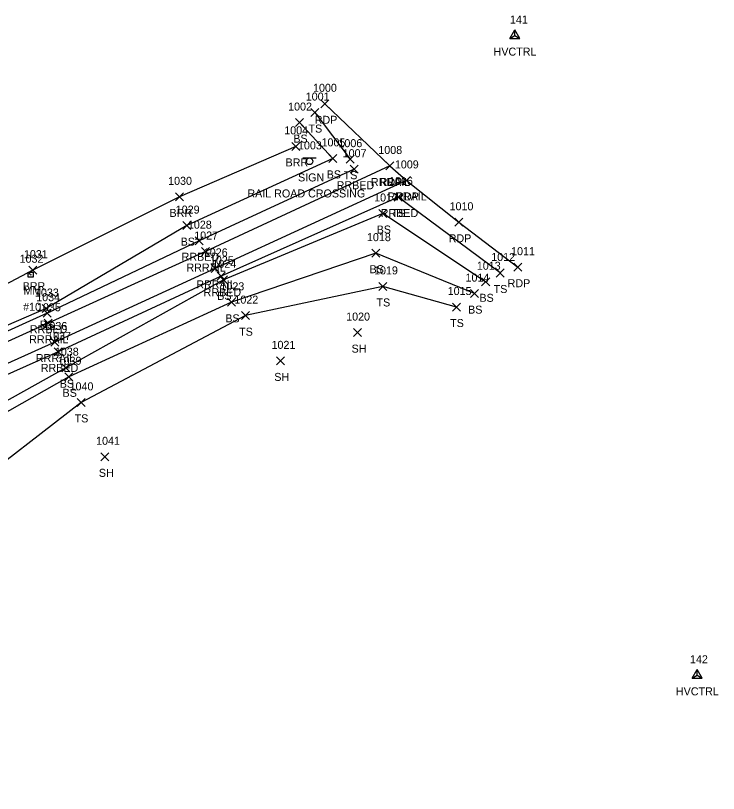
# Model space of a CAD drawing. Extents: x 1640777 to 1641692, y 610911 to 611377.
# Drawn here: x 1641516.6 to 1641692, y 611162.7 to 611356.9 of the extents above; entities that cross this region are included whole.
import ezdxf

# ---------------------------------------------------------------- set-up
doc = ezdxf.new("R2010")
doc.units = 0
for name, color, linetype in [('C_A', 7, 'Continuous'), ('C_I', 7, 'Continuous'), ('CPSM', 7, 'Continuous'), ('L_A', 7, 'Continuous'), ('L_I', 7, 'Continuous'), ('L_TIC', 7, 'Continuous'), ('LABL', 7, 'Continuous'), ('LELB', 7, 'Continuous'), ('P_A', 7, 'Continuous'), ('P_I', 7, 'Continuous'), ('P_TIC', 7, 'Continuous'), ('PET', 7, 'Continuous'), ('R_A', 7, 'Continuous'), ('R_I', 7, 'Continuous'), ('R_TIC', 7, 'Continuous'), ('RR', 7, 'Continuous'), ('RRB', 7, 'Continuous'), ('S_A', 7, 'Continuous'), ('S_C', 7, 'Continuous'), ('S_I', 7, 'Continuous'), ('SRM', 7, 'Continuous'), ('SSGN', 7, 'Continuous')]:
    doc.layers.add(name, color=color, linetype=linetype)

msp = doc.modelspace()

# ---------------------------------------------------------------- linework, layer by layer
at = {"layer": 'CPSM'}
for p, q in [((1641639.94, 611351.19), (1641641.19, 611353.35)), ((1641642.44, 611351.19), (1641641.19, 611353.35)), ((1641641.19, 611351.91), (1641641.19, 611353.35)), ((1641639.94, 611351.19), (1641641.19, 611351.91)), ((1641639.94, 611351.19), (1641642.44, 611351.19)), ((1641641.19, 611351.91), (1641641.19, 611351.91)), ((1641641.19, 611351.91), (1641642.44, 611351.19)), ((1641685.45, 611191.48), (1641686.7, 611193.64)), ((1641687.95, 611191.48), (1641686.7, 611193.64)), ((1641686.7, 611192.2), (1641686.7, 611193.64)), ((1641685.45, 611191.48), (1641686.7, 611192.2)), ((1641685.45, 611191.48), (1641687.95, 611191.48)), ((1641686.7, 611192.2), (1641686.7, 611192.2)), ((1641686.7, 611192.2), (1641687.95, 611191.48))]:
    msp.add_line(p, q, dxfattribs=at)
at = {"layer": 'L_TIC'}
for points in [[(1641590.27, 611331.69), (1641592.27, 611333.69)], [(1641592.27, 611331.69), (1641590.27, 611333.69)], [(1641586.44, 611329.19), (1641588.44, 611331.19)], [(1641588.44, 611329.19), (1641586.44, 611331.19)], [(1641585.48, 611323.25), (1641587.48, 611325.25)], [(1641587.48, 611323.25), (1641585.48, 611325.25)], [(1641594.78, 611320.25), (1641596.78, 611322.25)], [(1641596.78, 611320.25), (1641594.78, 611322.25)], [(1641599.06, 611320.05), (1641601.06, 611322.05)], [(1641601.06, 611320.05), (1641599.06, 611322.05)], [(1641556.5, 611310.65), (1641558.5, 611312.65)], [(1641558.5, 611310.65), (1641556.5, 611312.65)], [(1641611.04, 611310.61), (1641613.04, 611312.61)], [(1641613.04, 611310.61), (1641611.04, 611312.61)], [(1641607.26, 611306.49), (1641609.26, 611308.49)], [(1641609.26, 611306.49), (1641607.26, 611308.49)], [(1641558.33, 611303.47), (1641560.33, 611305.47)], [(1641560.33, 611303.47), (1641558.33, 611305.47)], [(1641605.47, 611296.59), (1641607.47, 611298.59)], [(1641607.47, 611296.59), (1641605.47, 611298.59)], [(1641519.84, 611292.34), (1641521.84, 611294.34)], [(1641521.84, 611292.34), (1641519.84, 611294.34)], [(1641636.49, 611291.64), (1641638.49, 611293.64)], [(1641638.49, 611291.64), (1641636.49, 611293.64)], [(1641567.47, 611289.94), (1641569.47, 611291.94)], [(1641569.47, 611289.94), (1641567.47, 611291.94)], [(1641632.9, 611289.45), (1641634.9, 611291.45)], [(1641634.9, 611289.45), (1641632.9, 611291.45)], [(1641607.25, 611288.29), (1641609.25, 611290.29)], [(1641609.25, 611288.29), (1641607.25, 611290.29)], [(1641630.08, 611286.49), (1641632.08, 611288.49)], [(1641632.08, 611286.49), (1641630.08, 611288.49)], [(1641523.18, 611282.76), (1641525.18, 611284.76)], [(1641525.18, 611282.76), (1641523.18, 611284.76)], [(1641569.47, 611284.32), (1641571.47, 611286.32)], [(1641571.47, 611284.32), (1641569.47, 611286.32)], [(1641625.63, 611283.15), (1641627.63, 611285.15)], [(1641627.63, 611283.15), (1641625.63, 611285.15)], [(1641572.95, 611280.99), (1641574.95, 611282.99)], [(1641574.95, 611280.99), (1641572.95, 611282.99)], [(1641600.94, 611276.76), (1641602.94, 611278.76)], [(1641602.94, 611276.76), (1641600.94, 611278.76)], [(1641581.65, 611269.7), (1641583.65, 611271.7)], [(1641583.65, 611269.7), (1641581.65, 611271.7)], [(1641528.14, 611268), (1641530.14, 611270)], [(1641530.14, 611268), (1641528.14, 611270)], [(1641528.85, 611265.73), (1641530.85, 611267.73)], [(1641530.85, 611265.73), (1641528.85, 611267.73)], [(1641531.9, 611259.34), (1641533.9, 611261.34)], [(1641533.9, 611259.34), (1641531.9, 611261.34)], [(1641537.87, 611245.75), (1641539.87, 611247.75)], [(1641539.87, 611245.75), (1641537.87, 611247.75)]]:
    msp.add_lwpolyline(points, dxfattribs=at)
at = {"layer": 'LABL'}
msp.add_lwpolyline([(1641586.48, 611324.25), (1641557.5, 611311.65), (1641520.84, 611293.34), (1641476.91, 611270.1), (1641461.92, 611262.06)], dxfattribs=at)
at = {"layer": 'LELB'}
for points in [[(1641591.27, 611332.69), (1641600.06, 611321.05)], [(1641587.44, 611330.19), (1641595.78, 611321.25), (1641559.33, 611304.47), (1641524.18, 611283.76), (1641479.77, 611264.52), (1641462.19, 611257.93), (1641450.98, 611252.58), (1641429.67, 611243.2)], [(1641637.49, 611292.64), (1641612.04, 611311.61)], [(1641633.9, 611290.45), (1641608.26, 611307.49), (1641568.47, 611290.94), (1641529.14, 611269), (1641489.56, 611246.95), (1641477.34, 611235.54), (1641471.45, 611231.22), (1641468.15, 611229.35), (1641466.43, 611220.85), (1641466.05, 611213.97)], [(1641631.08, 611287.49), (1641606.47, 611297.59), (1641570.47, 611285.32), (1641529.85, 611266.73), (1641490.88, 611244.68), (1641483.8, 611238.22)], [(1641626.63, 611284.15), (1641608.25, 611289.29), (1641573.95, 611281.99), (1641532.9, 611260.34), (1641503.67, 611237.69)]]:
    msp.add_lwpolyline(points, dxfattribs=at)
at = {"layer": 'P_TIC'}
for points in [[(1641592.74, 611333.88), (1641594.74, 611335.88)], [(1641594.74, 611333.88), (1641592.74, 611335.88)], [(1641608.96, 611318.36), (1641610.96, 611320.36)], [(1641610.96, 611318.36), (1641608.96, 611320.36)], [(1641613.1, 611314.75), (1641615.1, 611316.75)], [(1641615.1, 611314.75), (1641613.1, 611316.75)], [(1641626.18, 611304.3), (1641628.18, 611306.3)], [(1641628.18, 611304.3), (1641626.18, 611306.3)], [(1641640.89, 611293.09), (1641642.89, 611295.09)], [(1641642.89, 611293.09), (1641640.89, 611295.09)]]:
    msp.add_lwpolyline(points, dxfattribs=at)
at = {"layer": 'PET'}
msp.add_lwpolyline([(1641593.74, 611334.88), (1641609.96, 611319.36), (1641614.1, 611315.75), (1641627.18, 611305.3), (1641641.89, 611294.09)], dxfattribs=at)
at = {"layer": 'R_TIC'}
for points in [[(1641600.06, 611317.54), (1641602.06, 611319.54)], [(1641602.06, 611317.54), (1641600.06, 611319.54)], [(1641608.96, 611318.36), (1641610.96, 611320.36)], [(1641610.96, 611318.36), (1641608.96, 611320.36)], [(1641613.1, 611314.75), (1641615.1, 611316.75)], [(1641615.1, 611314.75), (1641613.1, 611316.75)], [(1641611.04, 611310.61), (1641613.04, 611312.61)], [(1641613.04, 611310.61), (1641611.04, 611312.61)], [(1641561.35, 611299.7), (1641563.35, 611301.7)], [(1641563.35, 611299.7), (1641561.35, 611301.7)], [(1641562.93, 611297), (1641564.93, 611299)], [(1641564.93, 611297), (1641562.93, 611299)], [(1641565.38, 611292.79), (1641567.38, 611294.79)], [(1641567.38, 611292.79), (1641565.38, 611294.79)], [(1641566.84, 611290.83), (1641568.84, 611292.83)], [(1641568.84, 611290.83), (1641566.84, 611292.83)], [(1641523.48, 611281.6), (1641525.48, 611283.6)], [(1641525.48, 611281.6), (1641523.48, 611283.6)], [(1641523.67, 611279.09), (1641525.67, 611281.09)], [(1641525.67, 611279.09), (1641523.67, 611281.09)], [(1641525.34, 611274.4), (1641527.34, 611276.4)], [(1641527.34, 611274.4), (1641525.34, 611276.4)], [(1641526.22, 611271.95), (1641528.22, 611273.95)], [(1641528.22, 611271.95), (1641526.22, 611273.95)]]:
    msp.add_lwpolyline(points, dxfattribs=at)
at = {"layer": 'RR'}
for points in [[(1641609.96, 611319.36), (1641563.93, 611298), (1641524.67, 611280.09), (1641481.95, 611260.74), (1641425.41, 611235.68), (1641374.39, 611212.53), (1641348.91, 611200.83), (1641315.51, 611185.65), (1641281.43, 611170.17)], [(1641614.1, 611315.75), (1641566.38, 611293.79), (1641526.34, 611275.4), (1641484.31, 611256.48), (1641427.45, 611231.21), (1641376.17, 611207.95), (1641351.03, 611196.44), (1641317.13, 611181.1), (1641283.87, 611165.86)]]:
    msp.add_lwpolyline(points, dxfattribs=at)
at = {"layer": 'RRB'}
for points in [[(1641601.06, 611318.54), (1641562.35, 611300.7), (1641524.48, 611282.6), (1641480.55, 611262.73), (1641424.68, 611238.55), (1641410.57, 611231.91), (1641373.51, 611214.53), (1641347.89, 611203.18), (1641314.84, 611187.71), (1641280.56, 611172.25)], [(1641612.04, 611311.61), (1641567.84, 611291.83), (1641527.22, 611272.95), (1641485.65, 611254.42), (1641428.83, 611228.82), (1641404.18, 611218.43), (1641376.76, 611205.98), (1641350.39, 611191.7), (1641314.2, 611175.58), (1641286.94, 611162.71)]]:
    msp.add_lwpolyline(points, dxfattribs=at)
at = {"layer": 'SRM'}
msp.add_lwpolyline([(1641519.71, 611292.82), (1641520.96, 611292.82), (1641520.96, 611291.57), (1641519.71, 611291.57)], close=True, dxfattribs=at)
msp.add_circle((1641520.33, 611292.2), 0.0833, dxfattribs=at)
at = {"layer": 'SSGN'}
for p, q in [((1641588.28, 611321.36), (1641591.62, 611321.36)), ((1641589.93, 611320.52), (1641589.93, 611320.52))]:
    msp.add_line(p, q, dxfattribs=at)
msp.add_circle((1641589.93, 611320.52), 0.833, dxfattribs=at)

# ---------------------------------------------------------------- texts
at = {"layer": 'C_A'}
for p in [(1641635.88, 611346.91), (1641681.39, 611187.2)]:
    msp.add_text('HVCTRL', height=2, dxfattribs=at).set_placement(p)
at = {"layer": 'C_I'}
for s, p in [('141', (1641639.96, 611354.91)), ('142', (1641684.9, 611195.2))]:
    msp.add_text(s, height=2, dxfattribs=at).set_placement(p)
at = {"layer": 'L_A'}
for s, p in [('TS', (1641589.68, 611327.69)), ('BS', (1641585.89, 611325.19)), ('BRR', (1641583.96, 611319.25)), ('BS', (1641594.22, 611316.25)), ('TS', (1641598.46, 611316.05)), ('BRR', (1641554.98, 611306.65)), ('TS', (1641610.45, 611306.61)), ('BS', (1641606.7, 611302.49)), ('BS', (1641557.77, 611299.47)), ('BS', (1641604.92, 611292.59)), ('BRR', (1641518.33, 611288.34)), ('TS', (1641635.9, 611287.64)), ('BS', (1641566.91, 611285.94)), ('BS', (1641632.34, 611285.45)), ('TS', (1641606.66, 611284.29)), ('BS', (1641629.52, 611282.49)), ('BS', (1641522.62, 611278.76)), ('BS', (1641568.92, 611280.32)), ('TS', (1641625.04, 611279.15)), ('TS', (1641572.36, 611276.99)), ('SH', (1641600.43, 611272.76)), ('SH', (1641581.14, 611265.7)), ('BS', (1641527.58, 611264)), ('BS', (1641528.29, 611261.73)), ('TS', (1641531.31, 611255.34)), ('SH', (1641537.35, 611241.75))]:
    msp.add_text(s, height=2, dxfattribs=at).set_placement(p)
at = {"layer": 'L_I'}
for s, p in [('1001', (1641588.99, 611335.69)), ('1002', (1641584.59, 611333.19)), ('1004', (1641583.63, 611327.25)), ('1005', (1641592.93, 611324.25)), ('1006', (1641597.15, 611324.05)), ('1030', (1641554.64, 611314.65)), ('1016', (1641609.78, 611314.61)), ('1017', (1641606.06, 611310.49)), ('1029', (1641556.55, 611307.47)), ('1018', (1641604.27, 611300.59)), ('1031', (1641518.64, 611296.34)), ('1012', (1641635.29, 611295.64)), ('1024', (1641565.7, 611293.94)), ('1019', (1641606.04, 611292.29)), ('1013', (1641631.69, 611293.45)), ('1014', (1641628.87, 611290.49)), ('1023', (1641567.7, 611288.32)), ('1033', (1641521.41, 611286.76)), ('1015', (1641624.42, 611287.15)), ('1022', (1641571.18, 611284.99)), ('1020', (1641599.08, 611280.76)), ('1021', (1641580.45, 611273.7)), ('1038', (1641526.37, 611272)), ('1039', (1641527.07, 611269.73)), ('1040', (1641530.04, 611263.34)), ('1041', (1641536.66, 611249.75))]:
    msp.add_text(s, height=2, dxfattribs=at).set_placement(p)
at = {"layer": 'P_A'}
for p in [(1641591.23, 611329.88), (1641607.45, 611314.36), (1641611.58, 611310.75), (1641624.67, 611300.3), (1641639.38, 611289.09)]:
    msp.add_text('RDP', height=2, dxfattribs=at).set_placement(p)
at = {"layer": 'P_I'}
for s, p in [('1000', (1641590.81, 611337.88)), ('1008', (1641607.11, 611322.36)), ('1009', (1641611.24, 611318.75)), ('1010', (1641624.89, 611308.3)), ('1011', (1641640.25, 611297.09))]:
    msp.add_text(s, height=2, dxfattribs=at).set_placement(p)
at = {"layer": 'R_A'}
for s, p in [('RRRAIL', (1641605.25, 611314.36)), ('RRBED', (1641596.71, 611313.54)), ('RRRAIL', (1641609.39, 611310.75)), ('RRBED', (1641607.69, 611306.61)), ('RRBED', (1641558, 611295.7)), ('RRRAIL', (1641559.22, 611293)), ('RRRAIL', (1641561.67, 611288.79)), ('RRBED', (1641563.49, 611286.83)), ('RRBED', (1641520.13, 611277.6)), ('RRRAIL', (1641519.96, 611275.09)), ('RRRAIL', (1641521.63, 611270.4)), ('RRBED', (1641522.86, 611267.95))]:
    msp.add_text(s, height=2, dxfattribs=at).set_placement(p)
at = {"layer": 'R_I'}
for s, p in [('1007', (1641598.21, 611321.54)), ('1008', (1641607.11, 611322.36)), ('1009', (1641611.24, 611318.75)), ('1016', (1641609.78, 611314.61)), ('1028', (1641559.58, 611303.7)), ('1027', (1641561.15, 611301)), ('1026', (1641563.55, 611296.79)), ('1025', (1641565.07, 611294.83)), ('1034', (1641521.71, 611285.6)), ('1035', (1641521.9, 611283.09)), ('1036', (1641523.52, 611278.4)), ('1037', (1641524.45, 611275.95))]:
    msp.add_text(s, height=2, dxfattribs=at).set_placement(p)
at = {"layer": 'S_A'}
for s, p in [('SIGN', (1641587.07, 611315.5)), ('MM', (1641518.52, 611287.2))]:
    msp.add_text(s, height=2, dxfattribs=at).set_placement(p)
at = {"layer": 'S_C'}
for s, p in [('RAIL ROAD CROSSING', (1641574.42, 611311.5)), ('#10', (1641518.45, 611283.2))]:
    msp.add_text(s, height=2, dxfattribs=at).set_placement(p)
at = {"layer": 'S_I'}
for s, p in [('1003', (1641587.06, 611323.5)), ('1032', (1641517.56, 611295.2))]:
    msp.add_text(s, height=2, dxfattribs=at).set_placement(p)

doc.saveas('drawing.dxf')
